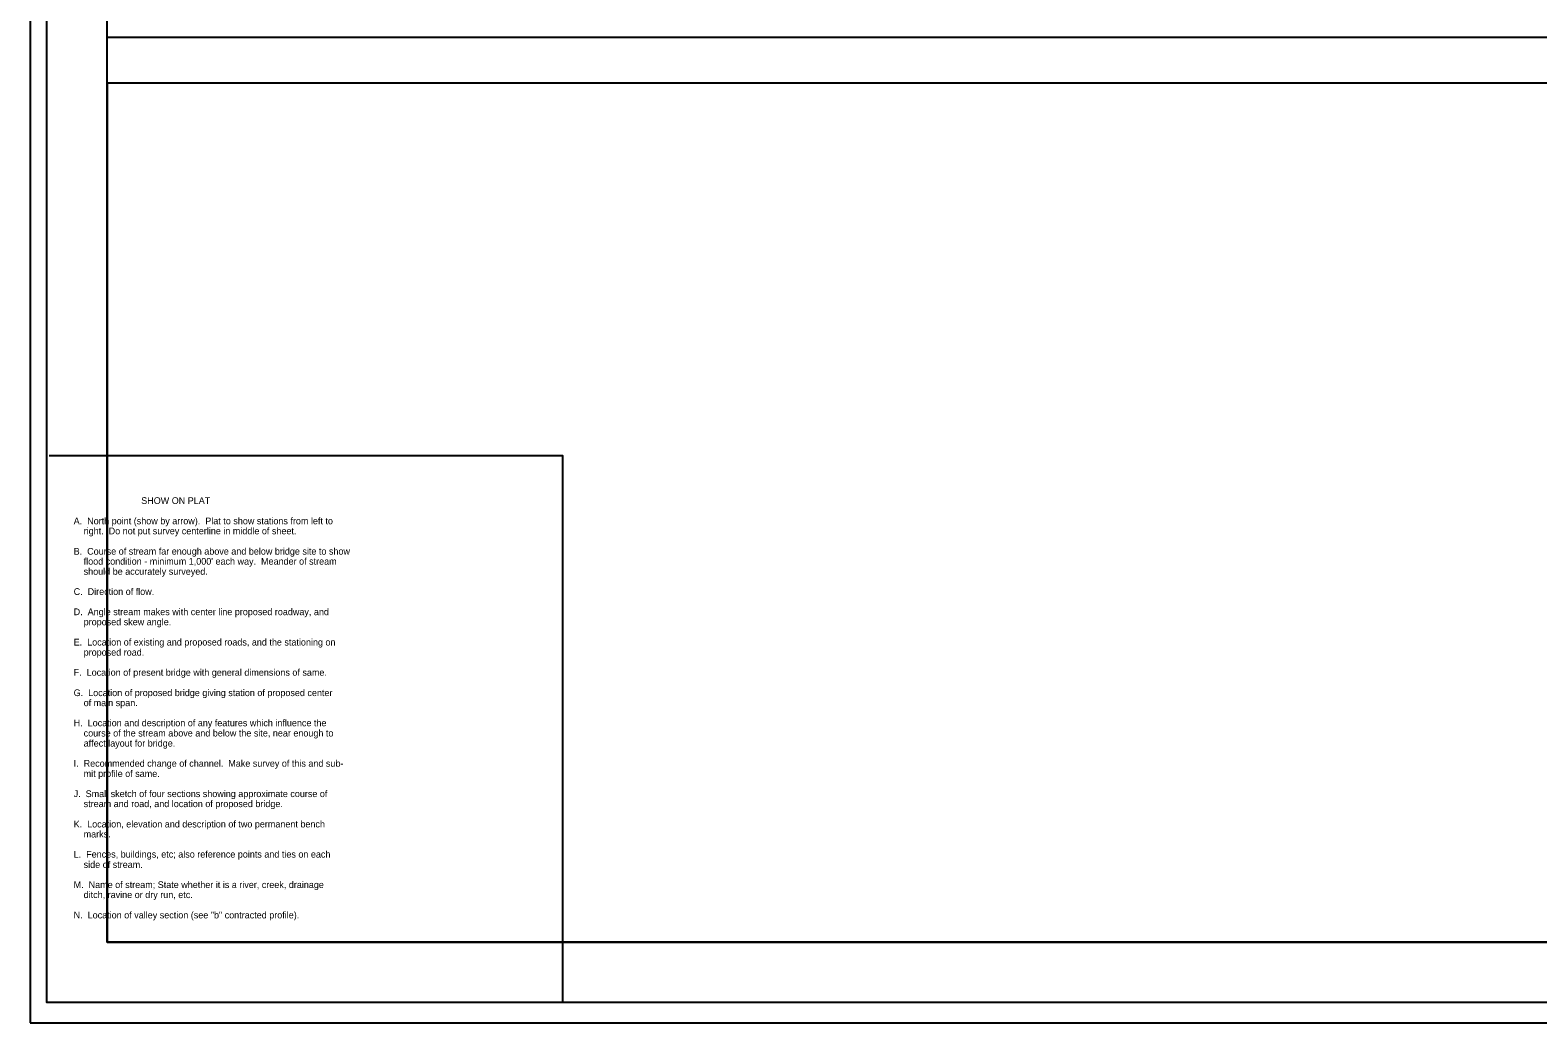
# Model space of a CAD drawing. Extents: x 0 to 31.6, y 0 to 20.8.
# Drawn here: x 0 to 15.8, y 0 to 10.4 of the extents above; entities that cross this region are included whole.
import ezdxf

# ---------------------------------------------------------------- set-up
doc = ezdxf.new("R2010")
doc.units = 0
for name, color, linetype in [('Border-Border', 7, 'Continuous'), ('Border-Bridge survey note', 7, 'Continuous'), ('Border-Full plan shape', 7, 'Continuous'), ('Border-Full profile shape', 7, 'Continuous'), ('Border-Plan bottom shape', 7, 'Continuous'), ('Border-Plotting block', 7, 'Continuous'), ('Border-Profile bottom shape', 7, 'Continuous'), ('Border-Xsection shape', 7, 'Continuous')]:
    doc.layers.add(name, color=color, linetype=linetype)

msp = doc.modelspace()

# ---------------------------------------------------------------- linework, layer by layer
at = {"layer": 'Border-Border'}
for p, q in [((0.175, 0.212), (0.175, 20.587)), ((31.425, 0.212), (0.175, 0.212))]:
    msp.add_line(p, q, dxfattribs=at)
at = {"layer": 'Border-Bridge survey note'}
msp.add_lwpolyline([(0.198, 5.945), (5.579, 5.945), (5.579, 0.212)], dxfattribs=at)
at = {"layer": 'Border-Full plan shape'}
msp.add_lwpolyline([(0.806, 19.956), (28.806, 19.956), (28.806, 0.844), (0.806, 0.844)], close=True, dxfattribs=at)
at = {"layer": 'Border-Full profile shape'}
msp.add_lwpolyline([(0.806, 19.956), (28.806, 19.956), (28.806, 0.844), (0.806, 0.844)], close=True, dxfattribs=at)
at = {"layer": 'Border-Plan bottom shape'}
msp.add_lwpolyline([(0.806, 10.325), (28.806, 10.325), (28.806, 0.844), (0.806, 0.844)], close=True, dxfattribs=at)
at = {"layer": 'Border-Plotting block'}
msp.add_lwpolyline([(0, 0), (31.6, 0), (31.6, 20.8), (0, 20.8)], close=True, dxfattribs=at)
at = {"layer": 'Border-Profile bottom shape'}
msp.add_lwpolyline([(0.806, 0.844), (28.806, 0.844), (28.806, 9.844), (0.806, 9.844)], close=True, dxfattribs=at)
at = {"layer": 'Border-Xsection shape'}
msp.add_lwpolyline([(29.417, 0.212), (0.175, 0.212), (0.175, 20.588), (29.417, 20.588)], close=True, dxfattribs=at)

# ---------------------------------------------------------------- texts
at = {"layer": 'Border-Bridge survey note'}
for s, height, p in [('                           SHOW ON PLAT', 0.07056, (0.456, 5.436)), ('A.  North point (show by arrow).  Plat to show stations from left to', 0.07058, (0.456, 5.223)), ('    right.  Do not put survey centerline in middle of sheet.', 0.07058, (0.456, 5.118)), ('B.  Course of stream far enough above and below bridge site to show', 0.07056, (0.456, 4.905)), ("    flood condition - minimum 1,000' each way.  Meander of stream", 0.07056, (0.456, 4.8)), ('    should be accurately surveyed.', 0.07056, (0.456, 4.694)), ('C.  Direction of flow.', 0.07056, (0.456, 4.483)), ('D.  Angle stream makes with center line proposed roadway, and', 0.07056, (0.456, 4.271)), ('    proposed skew angle.', 0.07056, (0.456, 4.165)), ('E.  Location of existing and proposed roads, and the stationing on', 0.07056, (0.456, 3.953)), ('    proposed road.', 0.07056, (0.456, 3.847)), ('F.  Location of present bridge with general dimensions of same.', 0.07056, (0.456, 3.636)), ('G.  Location of proposed bridge giving station of proposed center', 0.07056, (0.456, 3.423)), ('    of main span.', 0.07056, (0.456, 3.318)), ('H.  Location and description of any features which influence the', 0.07056, (0.456, 3.107)), ('    course of the stream above and below the site, near enough to', 0.07056, (0.456, 3)), ('    affect layout for bridge.', 0.07056, (0.456, 2.894)), ('I.  Recommended change of channel.  Make survey of this and sub-', 0.07056, (0.456, 2.683)), ('    mit profile of same.', 0.07056, (0.456, 2.576)), ('J.  Small sketch of four sections showing approximate course of', 0.07056, (0.456, 2.365)), ('    stream and road, and location of proposed bridge.', 0.07056, (0.456, 2.26)), ('K.  Location, elevation and description of two permanent bench', 0.07056, (0.456, 2.047)), ('    marks.', 0.0706, (0.456, 1.942)), ('L.  Fences, buildings, etc; also reference points and ties on each', 0.07056, (0.456, 1.731)), ('    side of stream.', 0.07056, (0.456, 1.623)), ('M.  Name of stream; State whether it is a river, creek, drainage', 0.07056, (0.456, 1.412)), ('    ditch, ravine or dry run, etc.', 0.07056, (0.456, 1.307)), ('N.  Location of valley section (see "b" contracted profile).', 0.07056, (0.456, 1.094))]:
    msp.add_text(s, height=height, dxfattribs=at).set_placement(p)

doc.saveas('drawing.dxf')
